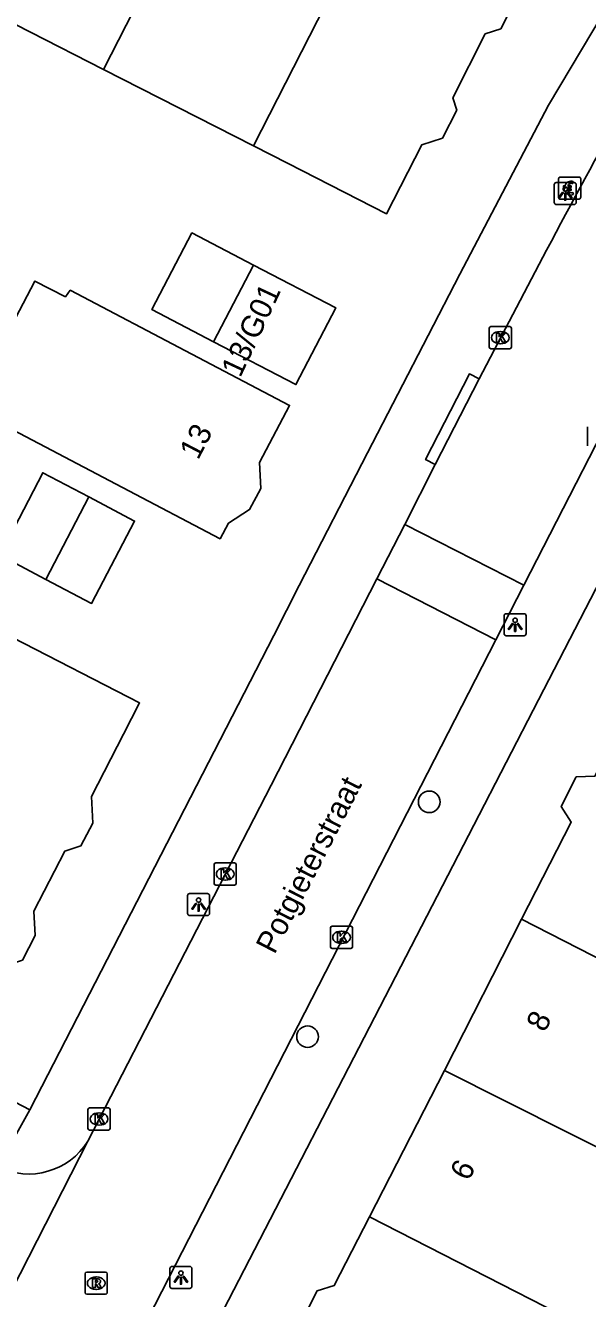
# Model space of a CAD drawing. Extents: x 160356 to 161355, y 381727 to 382845.
# Drawn here: x 161153.1 to 161178.6, y 382396.6 to 382454.3 of the extents above; entities that cross this region are included whole.
import ezdxf

# ---------------------------------------------------------------- set-up
doc = ezdxf.new("R2010")
doc.units = 0
for name, color, linetype in [('IMGEO_Betaalautomaat', 7, 'Continuous'), ('IMGEO_Boom', 7, 'Continuous'), ('IMGEO_Kolk', 7, 'Continuous'), ('IMGEO_Lichtpunt', 7, 'Continuous'), ('IMGEO_Openbare_ruimte_label', 7, 'Continuous'), ('IMGEO_Pand', 7, 'Continuous'), ('IMGEO_Pand_nummerreeks', 7, 'Continuous'), ('IMGEO_Rijbaan_lokaal_open', 7, 'Continuous'), ('IMGEO_Rioolput', 7, 'Continuous'), ('IMGEO_Voetpad_open', 7, 'Continuous')]:
    doc.layers.add(name, color=color, linetype=linetype)

msp = doc.modelspace()

# ---------------------------------------------------------------- linework, layer by layer
at = {"layer": 'IMGEO_Betaalautomaat'}
for p, q in [((161177.262, 382446.48), (161177.262, 382447.321)), ((161177.262, 382447.321), (161177.262, 382446.48)), ((161177.337, 382447.404), (161178.178, 382447.404)), ((161178.178, 382447.404), (161177.337, 382447.404)), ((161177.924, 382447.209), (161177.907, 382447.109)), ((161178.261, 382447.33), (161178.261, 382446.489)), ((161178.261, 382446.489), (161178.261, 382447.33)), ((161177.545, 382446.868), (161177.545, 382446.936)), ((161177.666, 382446.936), (161177.666, 382446.868)), ((161177.911, 382446.703), (161177.933, 382446.616)), ((161178.187, 382446.405), (161177.346, 382446.405)), ((161177.346, 382446.405), (161178.187, 382446.405))]:
    msp.add_line(p, q, dxfattribs=at)
for points in [[(161177.545, 382446.936), (161177.476, 382446.936), (161177.476, 382447.005), (161177.555, 382447.005)], [(161177.55, 382446.799), (161177.476, 382446.799), (161177.476, 382446.868), (161177.545, 382446.868)], [(161177.677, 382447.005), (161177.824, 382447.005), (161177.824, 382446.936), (161177.666, 382446.936)], [(161177.666, 382446.868), (161177.824, 382446.868), (161177.824, 382446.799), (161177.68, 382446.799)]]:
    msp.add_lwpolyline(points, dxfattribs=at)
for centre, radius, start, end in [((161177.34, 382447.327), 0.0779, 92.4484, 184.28452), ((161177.34, 382447.327), 0.0779, 92.4484, 184.28452), ((161177.838, 382446.929), 0.293, 73.01398, 165.01395), ((161178.184, 382447.327), 0.0779, 2.4484, 94.28452), ((161178.184, 382447.327), 0.0779, 2.4484, 94.28452), ((161177.811, 382446.854), 0.267, 191.80956, 297.03891), ((161177.844, 382446.942), 0.179, 69.32359, 159.56827), ((161177.844, 382446.869), 0.179, 202.76249, 291.86925), ((161177.34, 382446.483), 0.0779, 182.4484, 274.28452), ((161177.34, 382446.483), 0.0779, 182.4484, 274.28452), ((161178.184, 382446.483), 0.0779, 272.4484, 4.28452), ((161178.184, 382446.483), 0.0779, 272.4484, 4.28452)]:
    msp.add_arc(centre, radius, start, end, dxfattribs=at)
at = {"layer": 'IMGEO_Boom'}
for centre in [(161171.404, 382419.113), (161165.895, 382408.479)]:
    msp.add_circle(centre, 0.489, dxfattribs=at)
at = {"layer": 'IMGEO_Kolk'}
for p, q in [((161174.121, 382439.707), (161174.121, 382440.559)), ((161174.196, 382440.633), (161175.048, 382440.633)), ((161174.609, 382440.413), (161174.634, 382440.413)), ((161175.122, 382440.559), (161175.122, 382439.707)), ((161174.632, 382439.853), (161174.607, 382439.853)), ((161175.048, 382439.633), (161174.196, 382439.633)), ((161178.57, 382435.238), (161178.57, 382436.09)), ((161161.667, 382415.42), (161161.667, 382416.272)), ((161161.742, 382416.346), (161162.594, 382416.346)), ((161162.155, 382416.126), (161162.18, 382416.126)), ((161162.668, 382416.272), (161162.668, 382415.42)), ((161162.178, 382415.566), (161162.153, 382415.566)), ((161162.594, 382415.346), (161161.742, 382415.346)), ((161166.933, 382412.552), (161166.933, 382413.404)), ((161167.008, 382413.478), (161167.86, 382413.478)), ((161167.421, 382413.258), (161167.446, 382413.258)), ((161167.934, 382413.404), (161167.934, 382412.552)), ((161167.444, 382412.698), (161167.419, 382412.698)), ((161167.86, 382412.478), (161167.008, 382412.478)), ((161155.955, 382404.326), (161155.955, 382405.178)), ((161156.03, 382405.252), (161156.882, 382405.252)), ((161156.956, 382405.178), (161156.956, 382404.326)), ((161156.443, 382405.032), (161156.468, 382405.032)), ((161156.882, 382404.252), (161156.03, 382404.252)), ((161156.466, 382404.472), (161156.441, 382404.472))]:
    msp.add_line(p, q, dxfattribs=at)
for points in [[(161174.121, 382439.707), (161174.121, 382440.559)], [(161174.196, 382440.633), (161175.048, 382440.633)], [(161174.442, 382440.333), (161174.565, 382440.333), (161174.565, 382440.182), (161174.695, 382440.333), (161174.859, 382440.333), (161174.713, 382440.182), (161174.866, 382439.933), (161174.714, 382439.933), (161174.629, 382440.097), (161174.565, 382440.03), (161174.565, 382439.933), (161174.442, 382439.933), (161174.442, 382440.333)], [(161175.122, 382440.559), (161175.122, 382439.707)], [(161175.048, 382439.633), (161174.196, 382439.633)], [(161178.57, 382435.238), (161178.57, 382436.09)], [(161161.667, 382415.42), (161161.667, 382416.272)], [(161161.742, 382416.346), (161162.594, 382416.346)], [(161161.988, 382416.046), (161162.111, 382416.046), (161162.111, 382415.895), (161162.241, 382416.046), (161162.405, 382416.046), (161162.259, 382415.895), (161162.412, 382415.646), (161162.26, 382415.646), (161162.175, 382415.81), (161162.111, 382415.743), (161162.111, 382415.646), (161161.988, 382415.646), (161161.988, 382416.046)], [(161162.668, 382416.272), (161162.668, 382415.42)], [(161162.594, 382415.346), (161161.742, 382415.346)], [(161166.933, 382412.552), (161166.933, 382413.404)], [(161167.008, 382413.478), (161167.86, 382413.478)], [(161167.254, 382413.178), (161167.377, 382413.178), (161167.377, 382413.027), (161167.507, 382413.178), (161167.671, 382413.178), (161167.525, 382413.027), (161167.678, 382412.778), (161167.526, 382412.778), (161167.441, 382412.942), (161167.377, 382412.875), (161167.377, 382412.778), (161167.254, 382412.778), (161167.254, 382413.178)], [(161167.934, 382413.404), (161167.934, 382412.552)], [(161167.86, 382412.478), (161167.008, 382412.478)], [(161155.955, 382404.326), (161155.955, 382405.178)], [(161156.03, 382405.252), (161156.882, 382405.252)], [(161156.956, 382405.178), (161156.956, 382404.326)], [(161156.276, 382404.952), (161156.399, 382404.952), (161156.399, 382404.801), (161156.529, 382404.952), (161156.693, 382404.952), (161156.547, 382404.801), (161156.7, 382404.552), (161156.548, 382404.552), (161156.463, 382404.716), (161156.399, 382404.649), (161156.399, 382404.552), (161156.276, 382404.552), (161156.276, 382404.952)], [(161156.882, 382404.252), (161156.03, 382404.252)]]:
    msp.add_lwpolyline(points, dxfattribs=at)
for centre, start, end in [((161174.198, 382440.557), 91.55205, 178.44795), ((161174.198, 382440.557), 91.55205, 178.44795), ((161175.046, 382440.557), 1.55205, 88.44795), ((161175.046, 382440.557), 1.55205, 88.44795), ((161174.198, 382439.709), 181.55205, 268.44795), ((161174.198, 382439.709), 181.55205, 268.44795), ((161175.046, 382439.709), 271.55205, 358.44795), ((161175.046, 382439.709), 271.55205, 358.44795), ((161161.744, 382416.27), 91.55205, 178.44795), ((161161.744, 382416.27), 91.55205, 178.44795), ((161162.592, 382416.27), 1.55205, 88.44795), ((161162.592, 382416.27), 1.55205, 88.44795), ((161161.744, 382415.422), 181.55205, 268.44795), ((161161.744, 382415.422), 181.55205, 268.44795), ((161162.592, 382415.422), 271.55205, 358.44795), ((161162.592, 382415.422), 271.55205, 358.44795), ((161167.01, 382413.402), 91.55205, 178.44795), ((161167.01, 382413.402), 91.55205, 178.44795), ((161167.858, 382413.402), 1.55205, 88.44795), ((161167.858, 382413.402), 1.55205, 88.44795), ((161167.01, 382412.554), 181.55205, 268.44795), ((161167.01, 382412.554), 181.55205, 268.44795), ((161167.858, 382412.554), 271.55205, 358.44795), ((161167.858, 382412.554), 271.55205, 358.44795), ((161156.032, 382405.176), 91.55205, 178.44795), ((161156.032, 382405.176), 91.55205, 178.44795), ((161156.88, 382405.176), 1.55205, 88.44795), ((161156.88, 382405.176), 1.55205, 88.44795), ((161156.032, 382404.328), 181.55205, 268.44795), ((161156.032, 382404.328), 181.55205, 268.44795), ((161156.88, 382404.328), 271.55205, 358.44795), ((161156.88, 382404.328), 271.55205, 358.44795)]:
    msp.add_arc(centre, 0.0765, start, end, dxfattribs=at)
for centre, major_axis, ratio, start_param, end_param in [((161174.608, 382440.133), (-0.387, 0.002), 0.722429, 4.712389, 7.853982), ((161174.633, 382440.133), (-0.39, 0.002), 0.717154, 1.570796, 4.712389), ((161162.154, 382415.846), (-0.387, 0.002), 0.722429, 4.712389, 7.853982), ((161162.179, 382415.846), (-0.39, 0.002), 0.717154, 1.570796, 4.712389), ((161167.42, 382412.978), (-0.387, 0.002), 0.722429, 4.712389, 7.853982), ((161167.445, 382412.978), (-0.39, 0.002), 0.717154, 1.570796, 4.712389), ((161156.442, 382404.752), (-0.387, 0.002), 0.722429, 4.712389, 7.853982), ((161156.467, 382404.752), (-0.39, 0.002), 0.717154, 1.570796, 4.712389)]:
    msp.add_ellipse(centre, major_axis=major_axis, ratio=ratio, start_param=start_param, end_param=end_param, dxfattribs=at)
at = {"layer": 'IMGEO_Lichtpunt'}
for p, q in [((161177.062, 382447.063), (161177.062, 382446.256)), ((161177.062, 382447.063), (161177.062, 382446.256)), ((161177.964, 382447.158), (161177.156, 382447.158)), ((161177.964, 382447.158), (161177.156, 382447.158)), ((161178.058, 382446.256), (161178.058, 382447.063)), ((161178.058, 382446.256), (161178.058, 382447.063)), ((161177.156, 382446.162), (161177.964, 382446.162)), ((161177.156, 382446.162), (161177.964, 382446.162)), ((161175.696, 382427.633), (161174.888, 382427.633)), ((161175.696, 382427.633), (161174.888, 382427.633)), ((161174.794, 382427.538), (161174.794, 382426.731)), ((161174.794, 382427.538), (161174.794, 382426.731)), ((161175.79, 382426.731), (161175.79, 382427.538)), ((161175.79, 382426.731), (161175.79, 382427.538)), ((161174.888, 382426.637), (161175.696, 382426.637)), ((161174.888, 382426.637), (161175.696, 382426.637)), ((161161.364, 382414.962), (161160.556, 382414.962)), ((161161.364, 382414.962), (161160.556, 382414.962)), ((161160.462, 382414.867), (161160.462, 382414.06)), ((161160.462, 382414.867), (161160.462, 382414.06)), ((161161.458, 382414.06), (161161.458, 382414.867)), ((161161.458, 382414.06), (161161.458, 382414.867)), ((161160.556, 382413.966), (161161.364, 382413.966)), ((161160.556, 382413.966), (161161.364, 382413.966)), ((161159.663, 382397.979), (161159.663, 382397.172)), ((161159.663, 382397.979), (161159.663, 382397.172)), ((161160.565, 382398.074), (161159.757, 382398.074)), ((161160.565, 382398.074), (161159.757, 382398.074)), ((161160.659, 382397.172), (161160.659, 382397.979)), ((161160.659, 382397.172), (161160.659, 382397.979)), ((161159.757, 382397.078), (161160.565, 382397.078)), ((161159.757, 382397.078), (161160.565, 382397.078))]:
    msp.add_line(p, q, dxfattribs=at)
for points in [[(161177.436, 382446.727), (161177.475, 382446.699), (161177.287, 382446.437), (161177.249, 382446.464), (161177.436, 382446.727)], [(161177.538, 382446.679), (161177.585, 382446.679), (161177.585, 382446.357), (161177.538, 382446.357), (161177.538, 382446.679)], [(161177.648, 382446.699), (161177.686, 382446.726), (161177.873, 382446.464), (161177.834, 382446.436), (161177.648, 382446.699)], [(161175.168, 382427.202), (161175.207, 382427.174), (161175.019, 382426.912), (161174.981, 382426.939), (161175.168, 382427.202)], [(161175.27, 382427.154), (161175.317, 382427.154), (161175.317, 382426.832), (161175.27, 382426.832), (161175.27, 382427.154)], [(161175.38, 382427.174), (161175.418, 382427.201), (161175.605, 382426.939), (161175.566, 382426.911), (161175.38, 382427.174)], [(161160.836, 382414.531), (161160.875, 382414.503), (161160.687, 382414.241), (161160.649, 382414.268), (161160.836, 382414.531)], [(161160.938, 382414.483), (161160.985, 382414.483), (161160.985, 382414.161), (161160.938, 382414.161), (161160.938, 382414.483)], [(161161.048, 382414.503), (161161.086, 382414.53), (161161.273, 382414.268), (161161.234, 382414.24), (161161.048, 382414.503)], [(161160.037, 382397.643), (161160.076, 382397.615), (161159.888, 382397.353), (161159.85, 382397.38), (161160.037, 382397.643)], [(161160.139, 382397.595), (161160.186, 382397.595), (161160.186, 382397.273), (161160.139, 382397.273), (161160.139, 382397.595)], [(161160.249, 382397.615), (161160.287, 382397.642), (161160.474, 382397.38), (161160.435, 382397.352), (161160.249, 382397.615)]]:
    msp.add_lwpolyline(points, dxfattribs=at)
for centre in [(161177.561, 382446.861), (161175.293, 382427.336), (161160.961, 382414.665), (161160.162, 382397.777)]:
    msp.add_circle(centre, 0.0994, dxfattribs=at)
for centre, start, end in [((161177.156, 382447.063), 90, 180), ((161177.156, 382447.063), 90, 180), ((161177.964, 382447.063), 0, 90), ((161177.964, 382447.063), 0, 90), ((161177.156, 382446.256), 180, 270), ((161177.156, 382446.256), 180, 270), ((161177.964, 382446.256), 270, 0), ((161177.964, 382446.256), 270, 360), ((161174.888, 382427.538), 90, 180), ((161174.888, 382427.538), 90, 180), ((161175.696, 382427.538), 0, 90), ((161175.696, 382427.538), 0, 90), ((161174.888, 382426.731), 180, 270), ((161174.888, 382426.731), 180, 270), ((161175.696, 382426.731), 270, 0), ((161175.696, 382426.731), 270, 360), ((161160.556, 382414.867), 90, 180), ((161160.556, 382414.867), 90, 180), ((161161.364, 382414.867), 0, 90), ((161161.364, 382414.867), 0, 90), ((161160.556, 382414.06), 180, 270), ((161160.556, 382414.06), 180, 270), ((161161.364, 382414.06), 270, 0), ((161161.364, 382414.06), 270, 360), ((161159.757, 382397.979), 90, 180), ((161159.757, 382397.979), 90, 180), ((161160.565, 382397.979), 0, 90), ((161160.565, 382397.979), 0, 90), ((161159.757, 382397.172), 180, 270), ((161159.757, 382397.172), 180, 270), ((161160.565, 382397.172), 270, 0), ((161160.565, 382397.172), 270, 360)]:
    msp.add_arc(centre, 0.0946, start, end, dxfattribs=at)
at = {"layer": 'IMGEO_Pand'}
for points in [[(161156.66, 382452.28), (161162.466, 382463.655)], [(161169.249, 382460.187), (161163.444, 382448.814)], [(161163.444, 382448.814), (161165.012, 382448.013), (161169.464, 382445.738), (161171.062, 382448.867), (161172.001, 382449.172), (161172.649, 382450.439), (161172.468, 382450.998), (161173.942, 382453.885), (161174.64, 382454.112), (161175.156, 382455.121), (161175.09, 382456.399), (161175.443, 382457.09), (161174.559, 382457.542), (161174.092, 382458.262), (161173.072, 382458.782), (161172.099, 382458.732), (161169.249, 382460.187)], [(161150.994, 382458.209), (161151.257, 382458.075), (161150.028, 382455.669), (161156.66, 382452.28)], [(161163.444, 382448.814), (161156.66, 382452.28)], [(161163.454, 382443.422), (161160.657, 382444.878), (161158.847, 382441.401), (161161.643, 382439.945)], [(161161.643, 382439.945), (161163.454, 382443.422)], [(161161.643, 382439.945), (161165.365, 382438.007), (161167.175, 382441.484), (161163.454, 382443.422)], [(161160.658, 382439.388), (161155.154, 382442.277), (161154.935, 382441.981), (161153.556, 382442.697), (161150.383, 382436.651), (161151.771, 382435.923), (161151.977, 382436.253), (161157.51, 382433.351), (161161.937, 382431.027), (161162.31, 382431.738), (161163.27, 382432.345), (161163.773, 382433.303), (161163.726, 382434.477), (161165.085, 382437.064), (161160.658, 382439.388)], [(161154.041, 382429.188), (161151.962, 382430.279), (161153.906, 382434.012), (161155.986, 382432.921)], [(161155.986, 382432.921), (161158.065, 382431.83), (161156.121, 382428.096), (161154.041, 382429.188)], [(161154.041, 382429.188), (161155.986, 382432.921)], [(161145.928, 382413.676), (161148.322, 382412.445), (161148.616, 382411.529), (161149.661, 382410.992), (161151.008, 382411.057), (161151.711, 382410.696), (161152.223, 382411.692), (161152.989, 382411.938), (161153.563, 382413.055), (161153.509, 382414.161), (161154.908, 382416.883), (161155.633, 382417.115), (161156.168, 382418.155), (161156.11, 382419.35), (161157.564, 382422.179), (161158.29, 382423.591), (161152.537, 382426.549), (161151.812, 382425.136)], [(161175.587, 382413.794), (161177.836, 382418.191), (161177.377, 382418.9), (161178.062, 382420.239), (161178.904, 382420.282), (161179.403, 382421.258)], [(161172.088, 382406.955), (161175.587, 382413.794)], [(161175.587, 382413.794), (161187.173, 382407.865)], [(161168.697, 382400.328), (161172.088, 382406.955)], [(161183.346, 382401.295), (161172.088, 382406.955)], [(161165.481, 382394.081), (161165.833, 382394.769), (161165.588, 382395.528), (161166.323, 382396.965), (161167.106, 382397.218), (161168.697, 382400.328)], [(161186.152, 382391.403), (161182.627, 382393.201), (161168.697, 382400.328)]]:
    msp.add_lwpolyline(points, dxfattribs=at)
at = {"layer": 'IMGEO_Rijbaan_lokaal_open'}
for points in [[(161175.683, 382428.919), (161181.009, 382439.313), (161185.786, 382447.958)], [(161176.72, 382444.095), (161173.665, 382438.264)], [(161173.665, 382438.264), (161171.678, 382434.383)], [(161171.678, 382434.383), (161170.297, 382431.675)], [(161169.03, 382429.211), (161170.297, 382431.675)], [(161170.297, 382431.675), (161175.683, 382428.919)], [(161169.03, 382429.211), (161164.241, 382419.871), (161155.951, 382403.754)], [(161174.42, 382426.454), (161169.03, 382429.211)], [(161175.683, 382428.919), (161174.42, 382426.454)], [(161156.827, 382392.117), (161174.42, 382426.454)], [(161150.573, 382393.237), (161155.951, 382403.754)]]:
    msp.add_lwpolyline(points, dxfattribs=at)
for centre, radius, start, end in [((161389.843, 382332.127), 240.745, 148.7932, 152.28401), ((161153.274, 382405.407), 3.146, 243.66238, 328.31386)]:
    msp.add_arc(centre, radius, start, end, dxfattribs=at)
at = {"layer": 'IMGEO_Rioolput'}
for p, q in [((161155.827, 382396.892), (161155.827, 382397.744)), ((161155.902, 382397.818), (161156.754, 382397.818)), ((161156.315, 382397.598), (161156.34, 382397.598)), ((161156.828, 382397.744), (161156.828, 382396.892)), ((161156.338, 382397.038), (161156.313, 382397.038)), ((161156.754, 382396.818), (161155.902, 382396.818))]:
    msp.add_line(p, q, dxfattribs=at)
for points in [[(161155.827, 382396.892), (161155.827, 382397.744)], [(161155.902, 382397.818), (161156.754, 382397.818)], [(161156.828, 382397.744), (161156.828, 382396.892)], [(161156.416, 382397.516), (161156.164, 382397.518), (161156.164, 382397.118)], [(161156.164, 382397.118), (161156.288, 382397.118), (161156.288, 382397.28), (161156.299, 382397.28)], [(161156.342, 382397.437), (161156.288, 382397.437), (161156.288, 382397.356)], [(161156.288, 382397.356), (161156.34, 382397.356)], [(161156.346, 382397.251), (161156.417, 382397.118), (161156.557, 382397.118), (161156.492, 382397.244)], [(161156.754, 382396.818), (161155.902, 382396.818)]]:
    msp.add_lwpolyline(points, dxfattribs=at)
for centre, radius, start, end in [((161155.904, 382397.742), 0.0765, 91.55205, 178.44795), ((161155.904, 382397.742), 0.0765, 91.55205, 178.44795), ((161156.752, 382397.742), 0.0765, 1.55205, 88.44795), ((161156.752, 382397.742), 0.0765, 1.55205, 88.44795), ((161156.298, 382397.227), 0.0533, 26.02933, 88.69889), ((161156.324, 382397.545), 0.19, 274.7715, 282.96867), ((161156.348, 382397.341), 0.0964, 77.00612, 93.18647), ((161156.362, 382397.398), 0.0378, 276.66336, 79.67722), ((161156.415, 382397.406), 0.109, 350.36119, 89.41601), ((161156.413, 382397.406), 0.112, 277.58423, 350.98172), ((161156.397, 382397.191), 0.108, 29.51342, 73.79051), ((161155.904, 382396.894), 0.0765, 181.55205, 268.44795), ((161155.904, 382396.894), 0.0765, 181.55205, 268.44795), ((161156.752, 382396.894), 0.0765, 271.55205, 358.44795), ((161156.752, 382396.894), 0.0765, 271.55205, 358.44795)]:
    msp.add_arc(centre, radius, start, end, dxfattribs=at)
for centre, major_axis, ratio, start_param, end_param in [((161156.314, 382397.318), (-0.387, 0.002), 0.722429, 4.712389, 7.853982), ((161156.339, 382397.318), (-0.39, 0.002), 0.717154, 1.570796, 4.712389)]:
    msp.add_ellipse(centre, major_axis=major_axis, ratio=ratio, start_param=start_param, end_param=end_param, dxfattribs=at)
at = {"layer": 'IMGEO_Voetpad_open'}
for points in [[(161158.773, 382389.678), (161173.417, 382418.063), (161176.353, 382423.736), (161179.413, 382429.66), (161182.517, 382435.623), (161185.705, 382441.548), (161189.65, 382448.632), (161192.202, 382452.95), (161196.159, 382459.448), (161200.028, 382465.315), (161203.847, 382471.179), (161204.735, 382472.289), (161210.047, 382479.381), (161217.079, 382488.697)], [(161181.334, 382458.271), (161176.806, 382450.653), (161172.789, 382443), (161171.359, 382440.223), (161168.609, 382434.914), (161165.522, 382428.911), (161164.374, 382426.647), (161153.316, 382405.165)], [(161153.316, 382405.165), (161099.704, 382433.19), (161081.707, 382442.323), (161076.035, 382445.201)], [(161171.678, 382434.383), (161171.235, 382434.613), (161173.222, 382438.494), (161173.665, 382438.264)], [(161151.878, 382402.587), (161153.316, 382405.165)]]:
    msp.add_lwpolyline(points, dxfattribs=at)

# ---------------------------------------------------------------- texts
at = {"layer": 'IMGEO_Openbare_ruimte_label'}
msp.add_text('Potgieterstraat', height=1, rotation=62.79408, dxfattribs=at).set_placement((161164.399, 382412.171))
at = {"layer": 'IMGEO_Pand_nummerreeks'}
for s, rotation, p in [('13/G01', 64.93254, (161162.849, 382438.289)), ('13', 62.46016, (161160.937, 382434.558)), ('8', 62.90525, (161176.634, 382408.64)), ('6', 62.90525, (161173.187, 382401.903))]:
    msp.add_text(s, height=1, rotation=rotation, dxfattribs=at).set_placement(p)

doc.saveas('drawing.dxf')
